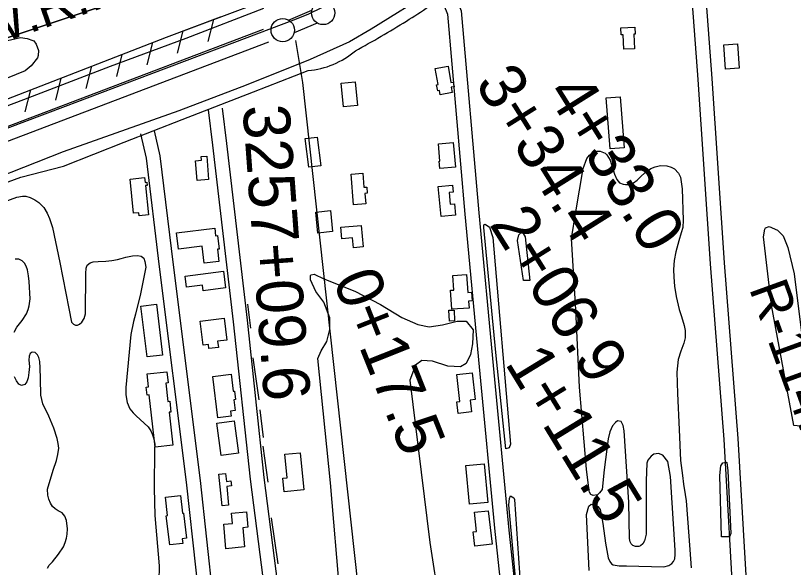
# Model space of a CAD drawing. Extents: x 3598634 to 3636690, y 517270 to 542944.
# Drawn here: x 3614405 to 3616071, y 532071 to 533253 of the extents above; entities that cross this region are included whole.
import ezdxf

# ---------------------------------------------------------------- set-up
doc = ezdxf.new("R2010")
doc.units = 0
for name, color, linetype in [('V-BLDG-OTLN', 7, 'Continuous'), ('V-FLOD-BASE', 7, 'Continuous'), ('V-LEVE-TOET', 7, 'Continuous'), ('V-RIVR-RANG-IDEN', 7, 'Continuous'), ('V-ROAD-CNTR', 7, 'Continuous'), ('V-RRAP-FSHR', 7, 'Continuous'), ('V-SITE-VEGE', 7, 'Continuous'), ('V-SURV-IDEN', 7, 'Continuous'), ('V-SURV-LINE', 7, 'Continuous'), ('V-TOPO-BNDY', 7, 'Continuous'), ('V-TOPO-DPTH', 7, 'Continuous'), ('V-TOPO-MINR', 7, 'Continuous'), ('V-TOPO-SHOR', 7, 'Continuous'), ('V-TOPO-WATR-IDEN', 7, 'Continuous')]:
    doc.layers.add(name, color=color, linetype=linetype)

msp = doc.modelspace()

# ---------------------------------------------------------------- linework, layer by layer
at = {"layer": 'V-BLDG-OTLN'}
for points in [[(3615707.5, 533180.7), (3615706.1, 533211.8), (3615701.8, 533211.6), (3615701.1, 533226.5), (3615731.3, 533227.9), (3615732, 533213.3), (3615729.2, 533213.1), (3615730.7, 533181.8)], [(3615925.2, 533138.2), (3615921.6, 533190.2), (3615951, 533192.2), (3615954.6, 533140.2)], [(3615310.3, 533105), (3615304.1, 533139.3), (3615331.4, 533144.3), (3615337.7, 533109.6), (3615342.5, 533110.5), (3615344.3, 533100.5), (3615338.3, 533099.4), (3615340.4, 533087.9), (3615314.8, 533083.2), (3615313.1, 533092.4), (3615309.3, 533091.7), (3615307, 533104.3)], [(3615132.3, 533111.1), (3615137.3, 533060.2), (3615107.8, 533057.3), (3615102.8, 533108.1)], [(3615699.8, 533079.2), (3615708.6, 532969.9), (3615678.8, 532967.5), (3615670.1, 533076.8)], [(3615033.4, 532928.2), (3615025.8, 532989.4), (3615051.4, 532992.5), (3615059, 532931.4)], [(3615314.2, 532941), (3615310.7, 532978.2), (3615342.1, 532981.1), (3615347.1, 532928.4), (3615313.6, 532925.2), (3615312.2, 532940.8)], [(3614814.7, 532952.2), (3614818.9, 532901.8), (3614794, 532899.7), (3614790.4, 532942.2), (3614803.3, 532943.3), (3614802.6, 532951.2)], [(3614658.3, 532829.6), (3614650.8, 532902.7), (3614681.8, 532905.9), (3614682.9, 532895.7), (3614686.5, 532896.1), (3614687.2, 532889.4), (3614683.7, 532889), (3614690.2, 532826.1), (3614669.8, 532824), (3614669.2, 532830.7)], [(3615128.8, 532847.9), (3615123.7, 532913.1), (3615148.7, 532915.1), (3615151, 532885.2), (3615157.5, 532885.7), (3615158.6, 532872.4), (3615153.4, 532872), (3615155.1, 532850)], [(3615316.4, 532822.4), (3615310.4, 532886.8), (3615340.9, 532889.6), (3615342.2, 532874.8), (3615333.8, 532874), (3615336.1, 532849.1), (3615345.3, 532850), (3615347.6, 532825.2)], [(3615052.6, 532787.3), (3615048.4, 532832.2), (3615080.1, 532835.2), (3615084.3, 532790.3)], [(3615102, 532799.6), (3615145.4, 532803.6), (3615149.6, 532757.7), (3615129, 532755.8), (3615127, 532777), (3615104.3, 532774.9)], [(3614750.1, 532787.8), (3614831.8, 532797.8), (3614833.8, 532781.3), (3614837.7, 532781.8), (3614841.2, 532753), (3614837.5, 532752.5), (3614840.7, 532726.4), (3614809.3, 532722.6), (3614804.9, 532759), (3614754.3, 532752.9)], [(3614768.6, 532695.1), (3614850.5, 532705.8), (3614855.2, 532669.8), (3614807.4, 532663.5), (3614805.8, 532675.6), (3614771.7, 532671.2)], [(3615339.8, 532624.1), (3615337, 532664.9), (3615344, 532665.3), (3615341.9, 532696.4), (3615371.2, 532698.3), (3615373.8, 532660.1), (3615381.8, 532660.6), (3615383.1, 532641.8), (3615375.5, 532641.3), (3615376.5, 532626.6)], [(3614687, 532522.1), (3614674, 532630.9), (3614707.1, 532634.9), (3614720.2, 532526.1)], [(3615344.3, 532622.5), (3615345.2, 532599.3), (3615334.3, 532598.9), (3615333.4, 532622.1)], [(3614807.1, 532547.3), (3614800.8, 532598.4), (3614852.3, 532604.8), (3614858.1, 532558.1), (3614838, 532555.6), (3614839.6, 532542.3), (3614819.6, 532539.8), (3614818.5, 532548.7)], [(3614734.2, 532403.7), (3614742.3, 532333.3), (3614704.5, 532329), (3614691.8, 532440.9), (3614686.9, 532440.3), (3614684.9, 532457.3), (3614690.2, 532458), (3614687, 532485.6), (3614729.5, 532490.5), (3614732.2, 532466.7), (3614727.3, 532466.1), (3614731.8, 532426.7), (3614735.4, 532427.1), (3614738, 532404.1)], [(3615356.8, 532426.4), (3615350.4, 532484.2), (3615382.9, 532487.8), (3615389.2, 532430.9), (3615378.6, 532429.7), (3615381.4, 532404.5), (3615352.8, 532401.3), (3615350.1, 532425.6)], [(3614838.6, 532392), (3614828.1, 532480.5), (3614866.8, 532485), (3614871.1, 532448.7), (3614874.1, 532449.1), (3614876.3, 532430.9), (3614873, 532430.5), (3614875.7, 532407.4), (3614865.6, 532406.2), (3614866.8, 532395.3)], [(3614873.7, 532385.4), (3614882.6, 532315.9), (3614845.5, 532311.2), (3614836.6, 532380.6)], [(3615014.8, 532317.1), (3615022.7, 532237.4), (3614980.4, 532233.2), (3614977.5, 532262.2), (3614987.1, 532263.2), (3614982.1, 532313.9)], [(3615408.9, 532293.2), (3615416.5, 532210.5), (3615377.2, 532206.9), (3615369.6, 532289.7)], [(3614847.5, 532203), (3614840.6, 532270.9), (3614855.2, 532272.3), (3614856.9, 532255.5), (3614866.7, 532256.5), (3614867.8, 532245.9), (3614857.5, 532244.9), (3614861.6, 532204.5)], [(3614765.2, 532187.6), (3614771.6, 532133.8), (3614762.4, 532132.7), (3614763.6, 532122.9), (3614735.5, 532119.6), (3614728.1, 532182.1), (3614731.1, 532182.5), (3614726.4, 532221.5), (3614758.5, 532225.3), (3614763, 532187.3)], [(3614891.8, 532156.5), (3614895.5, 532115.2), (3614856, 532111.6), (3614851.4, 532163.8), (3614870, 532165.4), (3614868.1, 532187.4), (3614900.1, 532190.3), (3614903.1, 532157.5)], [(3615392.4, 532148.5), (3615387.8, 532189.5), (3615417.6, 532192.8), (3615425.6, 532121.1), (3615388.8, 532117), (3615385.4, 532147.8)]]:
    msp.add_lwpolyline(points, close=True, dxfattribs=at)
at = {"layer": 'V-FLOD-BASE'}
msp.add_lwpolyline([(3614387.2, 533011.8), (3614512.1, 533058.6), (3614697.5, 533129.1), (3614874.7, 533196.2), (3615001.6, 533243.8), (3615032.2, 533255.6), (3615062.4, 533270.6), (3615109.1, 533298.8), (3615194, 533354.6), (3615258.7, 533396.4), (3615296.1, 533417.8), (3615348.7, 533441.2), (3615447.4, 533478.4), (3615574.9, 533521.1), (3615788.5, 533599.7), (3615916.2, 533643.6), (3616121.2, 533718.6)], dxfattribs=at)
at = {"layer": 'V-LEVE-TOET'}
for points in [[(3616566.3, 533821.7), (3616442.6, 533770.9), (3616303, 533687.8), (3616126.4, 533621.4), (3615917, 533547.8), (3615721.9, 533471), (3615586.2, 533423.2), (3615467.5, 533385.1), (3615352.2, 533340.3), (3615341, 533334.6), (3615300.4, 533307.4), (3615166.7, 533223.7), (3615120.5, 533196.5), (3615036.4, 533158.9), (3614899.5, 533103.8), (3614754.9, 533048.8), (3614507.1, 532961.2), (3614278.7, 532871)], [(3614936.5, 533267.9), (3614770, 533203.6), (3614607.9, 533143.9), (3614422.5, 533072.1), (3614215, 532994.1)]]:
    msp.add_lwpolyline(points, dxfattribs=at)
at = {"layer": 'V-ROAD-CNTR'}
for points in [[(3616038, 530652), (3616009, 531053.3), (3615987.9, 531393.3), (3615961, 531719.1), (3615945.1, 531955.4), (3615922.5, 532345.6), (3615893.3, 532721.6), (3615867.3, 533116.2), (3615846.6, 533392.5), (3615837.1, 533501.9)], [(3616068, 530654.2), (3616038.9, 531055.3), (3616017.9, 531395.4), (3615990.9, 531721.4), (3615975.1, 531957.3), (3615952.5, 532347.6), (3615923.2, 532723.7), (3615897.2, 533118.3), (3615876.5, 533394.9), (3615867, 533504.5)], [(3615343.7, 533302.5), (3615359.8, 533263), (3615397.4, 532830.4), (3615428.1, 532503.9), (3615461.4, 532151), (3615537.4, 531445.5)], [(3615315.9, 533291.3), (3615330.3, 533255.9), (3615367.5, 532827.7), (3615398.2, 532501.1), (3615431.5, 532148), (3615507.5, 531442.7)], [(3612226.4, 532062.1), (3612430.1, 532146.2), (3612651.1, 532229.1), (3612941.7, 532339.9), (3613141.7, 532411.5), (3613453.6, 532538.8), (3613757.3, 532652.7), (3614058.1, 532765.6), (3614367.4, 532889.4), (3614416.7, 532906.6), (3614507.9, 532930.4), (3614637.9, 532981.5), (3614762, 533030.3), (3614915, 533089.5), (3615031.8, 533135)], [(3615200.6, 529982), (3615165.3, 530267.4), (3615138.8, 530529.1), (3615101.4, 530859.6), (3615073.7, 531095.2), (3615042.2, 531378.2), (3615012.4, 531640.5), (3614982.2, 531918.9), (3614938, 532264), (3614901.9, 532600.6), (3614857.6, 532978.9), (3614848.3, 533054.9)], [(3615170.8, 529978.3), (3615135.5, 530264), (3615108.9, 530525.9), (3615071.6, 530856.2), (3615043.9, 531091.8), (3615012.4, 531374.8), (3614982.6, 531637.2), (3614952.4, 531915.4), (3614908.2, 532260.5), (3614872.1, 532597.3), (3614827.9, 532975.4), (3614818.5, 533051.3)], [(3614702.4, 533006), (3614714.4, 532952.7), (3614742.6, 532718.9), (3614800.8, 532257.4), (3614841.7, 531880.7), (3614887.6, 531469.1), (3614920.7, 531163.3)], [(3614673.1, 532999.4), (3614684.8, 532947.6), (3614712.9, 532715.2), (3614771, 532253.9), (3614811.9, 531877.5), (3614857.8, 531465.8), (3614890.9, 531160)]]:
    msp.add_lwpolyline(points, dxfattribs=at)
for centre, radius, start, end in [((3614893, 533824.3), 679.8, 300.9207, 305.76), ((3614097.6, 535081.6), 2167.5, 298.5352, 301.8792), ((3615016.7, 533313.1), 178.7, 274.8516, 310.625)]:
    msp.add_arc(centre, radius, start, end, dxfattribs=at)
at = {"layer": 'V-RRAP-FSHR'}
for p, q in [((3614829.3, 533244.6), (3614817.3, 533197.3)), ((3614763.8, 533219.9), (3614751.8, 533172.5)), ((3614698.4, 533194.9), (3614686.8, 533147.5)), ((3614633.2, 533169.6), (3614621.5, 533122.2)), ((3614567.9, 533144.3), (3614556.2, 533096.9)), ((3614502.6, 533119.1), (3614490.9, 533071.7)), ((3614437.3, 533093.8), (3614425.6, 533046.4))]:
    msp.add_line(p, q, dxfattribs=at)
for points in [[(3614277.5, 533031.9), (3614728.5, 533206.5), (3614988.3, 533304.6), (3615022.7, 533315.7), (3615059.6, 533337.4), (3615192.4, 533428.1), (3615236, 533457.2), (3615305.5, 533495.6), (3615349.8, 533508.8), (3615620.7, 533604.4), (3616010.3, 533745.9), (3616270.2, 533836.3), (3616286.7, 533857.9), (3616331.9, 533908.4), (3616365.5, 533937.7), (3616395.4, 533949.1), (3616467, 533968.2), (3617050.5, 534116.8)], [(3614085.6, 532958.7), (3614277.5, 533031.9), (3614728.5, 533206.5), (3614843.9, 533250.1)]]:
    msp.add_lwpolyline(points, dxfattribs=at)
at = {"layer": 'V-SITE-VEGE'}
for points in [[(3614347.6, 533190.3), (3614416.1, 533205.7), (3614430.4, 533203.4), (3614442.4, 533199.6), (3614444.3, 533198.9), (3614449.8, 533191.6), (3614454.5, 533177.7), (3614454.1, 533167.3), (3614452.6, 533162.7), (3614438.8, 533145.3), (3614426.1, 533134.8), (3614332.3, 533096.9)], [(3615633.4, 532065), (3615628.2, 532184.7), (3615632.7, 532202.9), (3615638, 532206.7), (3615644.3, 532206.5), (3615651.9, 532202), (3615657, 532195.4), (3615660.4, 532177.5), (3615663, 532165.6), (3615668.8, 532123.4), (3615674.5, 532092.3), (3615677.6, 532084.2), (3615681.7, 532079.2), (3615684.7, 532076.9), (3615698.1, 532074.7), (3615713.3, 532074.5), (3615793.6, 532072.9), (3615804.4, 532075.7), (3615810.7, 532079.6), (3615814.3, 532084.1), (3615817, 532089.7), (3615818, 532098.8), (3615817.9, 532108.4), (3615808, 532266.3), (3615802.3, 532298.4), (3615791.6, 532312), (3615782, 532315.3), (3615771.8, 532314), (3615766.5, 532309.9), (3615759.5, 532301), (3615756.8, 532294.7), (3615755.9, 532256.9), (3615755.8, 532142.8), (3615752.3, 532128.4), (3615748.8, 532122.3), (3615743.7, 532117.9), (3615740.2, 532116.4), (3615732.9, 532116.4), (3615727.3, 532118.1), (3615723.7, 532121.9), (3615721.7, 532126.4), (3615720.1, 532133.5), (3615718.2, 532211.4), (3615708.3, 532363.5), (3615706.7, 532375.4), (3615702.1, 532383.7), (3615694.5, 532385.5), (3615690, 532381.9), (3615683.2, 532374.3), (3615678, 532361.8), (3615674.2, 532346.9), (3615666, 532280.3), (3615661.6, 532238.2), (3615655.6, 532230.9), (3615651.1, 532226.5), (3615642.2, 532225.7), (3615636.9, 532227.7), (3615634.1, 532232.3), (3615633.3, 532235.6), (3615628.2, 532282.1), (3615612.7, 532457.2), (3615605, 532623.1), (3615595.9, 532775.5), (3615604.7, 532832.4), (3615620.7, 532925.7), (3615628.4, 532946.5), (3615634.4, 532953.8), (3615643.5, 532960.4), (3615650.3, 532962.3), (3615656.9, 532962.3), (3615667.6, 532958.5), (3615671.6, 532954.5), (3615678.5, 532943.2), (3615687.8, 532913.3), (3615692.9, 532902), (3615698.8, 532894.7), (3615706.1, 532891.7), (3615711.2, 532890.9), (3615719.8, 532891.5), (3615728.4, 532894.8), (3615736.2, 532900.7), (3615744, 532908.3), (3615752.6, 532916.2), (3615765.4, 532925.4)], [(3615765.4, 532925.4), (3615775, 532929.2), (3615786.2, 532931.6), (3615799.6, 532931.1), (3615809, 532928.4), (3615816.1, 532924.4), (3615825.2, 532915.3), (3615829.1, 532907.2), (3615833, 532882.2), (3615835.1, 532814.7), (3615833.9, 532798.9), (3615830.9, 532787.4), (3615825.6, 532770.8)], [(3614380.9, 532854.4), (3614408.5, 532864.2), (3614420.3, 532866.2), (3614427.2, 532866.1), (3614436.8, 532863.4), (3614446.4, 532858.6), (3614455.4, 532852.3), (3614465.7, 532841.6), (3614473.4, 532829.7), (3614478.1, 532818.5), (3614484.7, 532798.9), (3614499.9, 532724.3), (3614519.2, 532625.8), (3614525.3, 532596.5), (3614529.6, 532592), (3614533.5, 532589.8), (3614538.2, 532590.3), (3614542.6, 532592.1), (3614547.5, 532596.8), (3614552.5, 532604.6), (3614555.2, 532614.1), (3614555.6, 532700.8), (3614556.5, 532712.4), (3614558.6, 532718.5), (3614565.1, 532723.7), (3614571.7, 532725.3), (3614582.6, 532726.7), (3614598.8, 532727.4), (3614611.9, 532728.6), (3614623.8, 532730.8), (3614631.2, 532732.9), (3614641.9, 532735.7), (3614655.7, 532738.8), (3614666.3, 532739.3), (3614674.2, 532737.8), (3614680, 532733.4), (3614682.3, 532726.1), (3614684.3, 532714.3), (3614672.6, 532657.2), (3614662, 532613.7), (3614658.3, 532597.7), (3614652.5, 532570.2), (3614641.8, 532456.6), (3614641.8, 532440.7), (3614644.7, 532424.7), (3614650.1, 532411.1), (3614657.4, 532402.3), (3614664, 532395.7), (3614689.1, 532372.1), (3614694.8, 532364.1), (3614698.6, 532355), (3614701.5, 532346.4), (3614703.5, 532335), (3614703.2, 532325), (3614701.9, 532240.9), (3614703.3, 532182.4), (3614712.9, 532075.1), (3614712.4, 532041.8)], [(3615825.6, 532770.8), (3615819.4, 532747.4), (3615815.9, 532728.2), (3615814.2, 532709.4), (3615815.1, 532692.8), (3615816.2, 532673.5), (3615819.6, 532651.3), (3615826.1, 532623.9), (3615831.3, 532608.9), (3615836.8, 532589.3), (3615838.9, 532578.3), (3615839.4, 532563), (3615836.4, 532551.6), (3615830.2, 532534.7), (3615824.4, 532516.6), (3615821.5, 532489.6), (3615823, 532443.5), (3615826.4, 532366.6), (3615829.3, 532300.3), (3615833.6, 532268.5), (3615835.4, 532249.7), (3615838.9, 532227.3), (3615841, 532214.3), (3615847.2, 532138.7), (3615851.9, 532070.4)], [(3614428.8, 532614.3), (3614432.3, 532623.3), (3614434.8, 532631.6), (3614436.7, 532646.3), (3614434.6, 532683.6), (3614433, 532695.9), (3614430.7, 532708.2), (3614428.4, 532716.3), (3614424.4, 532723.1), (3614419.3, 532727.9), (3614412.4, 532731.1), (3614404.6, 532731.7)], [(3615100.1, 532008.4), (3615079.9, 532252.6), (3615052.8, 532518.5), (3615059.5, 532534.9), (3615071.6, 532555.3), (3615078.2, 532581.1), (3615078.1, 532605.5), (3615065.7, 532639.4), (3615048, 532662.4), (3615037, 532686.8), (3615036.9, 532696.3), (3615038.3, 532697.6), (3615045.1, 532699), (3615065.5, 532689.6), (3615132.1, 532662.8), (3615186.5, 532634.6), (3615232.8, 532606.3), (3615266.8, 532591.6), (3615291.3, 532586.3), (3615319.8, 532590.5), (3615351, 532598.8), (3615370, 532598.9), (3615385, 532579.9), (3615383.8, 532550.1), (3615379.8, 532527), (3615370.4, 532507.9), (3615358.2, 532501.1), (3615331.1, 532502.3), (3615298.5, 532513), (3615275.4, 532514.2), (3615261.9, 532504.7), (3615249.8, 532472), (3615292.3, 532124.8), (3615313.3, 531990.5)], [(3614402.7, 532575.4), (3614408.1, 532585.6), (3614419.6, 532599.9), (3614428.8, 532614.3)], [(3614473.8, 532069.9), (3614477.7, 532076.1), (3614484.2, 532083.7), (3614497.1, 532099.8), (3614508, 532115.4), (3614511.6, 532124.8), (3614514.4, 532134.1), (3614515.9, 532142.3), (3614516.6, 532154), (3614514.2, 532171.6), (3614510.8, 532181.3), (3614505.1, 532188), (3614497, 532192.9), (3614490.2, 532196.7), (3614484.2, 532201.8), (3614479.9, 532208.8), (3614476.8, 532217.3), (3614474.6, 532225.8), (3614473.8, 532238.9), (3614486.2, 532279.5), (3614492.9, 532300.3), (3614496.1, 532313.2), (3614498.1, 532326.4), (3614496.8, 532337), (3614494.3, 532347.4), (3614487.1, 532369.5), (3614476.8, 532394.9), (3614464.1, 532421.7), (3614459.9, 532440.5), (3614458.9, 532475.5), (3614458, 532498.7), (3614457.2, 532512.2), (3614455.2, 532520.6), (3614452.6, 532526.7), (3614447.4, 532531.2), (3614441.1, 532532.1), (3614436.9, 532529.6), (3614434.5, 532523.6), (3614434.1, 532515.3), (3614435.1, 532501.7), (3614433.8, 532488.6), (3614432.3, 532477.3), (3614429.7, 532468.4), (3614425.5, 532463.1), (3614418.5, 532460.7), (3614412.6, 532463.4), (3614407.3, 532470.9), (3614403.3, 532479.3)]]:
    msp.add_lwpolyline(points, dxfattribs=at)
for points in [[(3615455.5, 532325.1), (3615434.1, 532531.3), (3615408.3, 532799.4), (3615408.3, 532804.8), (3615411, 532806.2), (3615420.5, 532799.5), (3615427.4, 532777.8), (3615465, 532335.5), (3615462.3, 532327.3)], [(3615493, 532685.8), (3615480.4, 532771.3), (3615483, 532783.5), (3615488.4, 532789), (3615491.2, 532787.6), (3615492.5, 532786.3), (3615496.6, 532779.5), (3615506.6, 532685.9)], [(3616071.5, 532375.2), (3616024, 532632.9), (3616007, 532779.4), (3616009.6, 532795.7), (3616011, 532798.4), (3616019.1, 532801.2), (3616036.8, 532793.1), (3616049.1, 532781), (3616058.7, 532756.6), (3616072.6, 532699.6), (3616106.5, 532424.3), (3616105.3, 532394.4), (3616098.6, 532382.1), (3616086.4, 532373.9)], [(3615916.6, 532136.9), (3615913.2, 532268.5), (3615915.8, 532288.9), (3615919.9, 532295.7), (3615926.7, 532297.1), (3615928, 532295.8), (3615930.8, 532278.1), (3615936.9, 532143.8), (3615934.3, 532137)], [(3615481.7, 531987.3), (3615461.6, 532205.7), (3615462.8, 532219.3), (3615465.5, 532224.7), (3615472.3, 532220.7), (3615473.7, 532216.6), (3615488.4, 531996.8), (3615488.5, 531984.6)]]:
    msp.add_lwpolyline(points, close=True, dxfattribs=at)
at = {"layer": 'V-SURV-LINE'}
for points in [[(3614990, 533243.3), (3615039.8, 533264.4)], [(3615051.5, 533236.8), (3615001.7, 533215.7)], [(3613278.8, 532594), (3614936.6, 533223.9)], [(3614947.3, 533195.8), (3613289.5, 532565.9)]]:
    msp.add_lwpolyline(points, dxfattribs=at)
for centre in [(3615064, 533258.4), (3614977.4, 533221.7)]:
    msp.add_circle(centre, 25, dxfattribs=at)
at = {"layer": 'V-TOPO-BNDY'}
for p, q in [((3615020.3, 533109.9), (3615005.3, 533199.1)), ((3616153.6, 522800.8), (3615020.3, 533109.9))]:
    msp.add_line(p, q, dxfattribs=at)
at = {"layer": 'V-TOPO-DPTH'}
msp.add_lwpolyline([(3615118, 533449), (3614215.6, 533148.1)], dxfattribs=at)
at = {"layer": 'V-TOPO-MINR'}
msp.add_lwpolyline([(3614215.6, 533148.1), (3615118, 533449)], dxfattribs=at)
at = {"layer": 'V-TOPO-SHOR'}
for p, q in [((3614902.1, 532634.8), (3614908.5, 532583.5)), ((3614913.2, 532520.4), (3614926, 532430.4)), ((3614928.6, 532408.9), (3614935.8, 532349.7)), ((3614934.8, 532330.8), (3614945.4, 532253.7)), ((3614953, 532177.6), (3614966.7, 532079.2))]:
    msp.add_line(p, q, dxfattribs=at)

# ---------------------------------------------------------------- texts
at = {"layer": 'V-RIVR-RANG-IDEN'}
msp.add_text('R-114.8', height=83, rotation=289.9085, dxfattribs=at).set_placement((3615975.3, 532668.9))
at = {"layer": 'V-SURV-IDEN'}
for s, rotation, p in [('3+34.4', 302.0467, (3615387.5, 533107.3)), ('4+33.0', 302.0306, (3615540, 533087.2)), ('3257+09.6', 274.1976, (3614891.4, 533059.3)), ('2+06.9', 302.0802, (3615418.5, 532806.5)), ('0+17.5', 291.6853, (3615083.7, 532687.1)), ('1+11.5', 301.466, (3615451.8, 532508.7))]:
    msp.add_text(s, height=100, rotation=rotation, dxfattribs=at).set_placement(p)
at = {"layer": 'V-TOPO-WATR-IDEN'}
msp.add_text('L.W.R.P.', height=83, rotation=19.0621, dxfattribs=at).set_placement((3614248.8, 533150.2))

doc.saveas('drawing.dxf')
